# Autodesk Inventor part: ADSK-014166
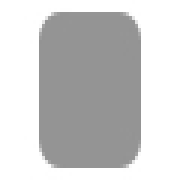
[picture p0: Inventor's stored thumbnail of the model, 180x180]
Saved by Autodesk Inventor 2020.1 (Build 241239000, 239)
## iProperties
Created: 2019-01
Part Number: ADSK-014166
Material: Stahl, weich
Document SubType Name: Modeling
Designer: lutzd
Language: de-DE
Size Designation: 5 x 60 x 40
Categories: <MemberInstance><Categories><Category DisplayName="Sonstige Bauteile" InternalName="5aa15e00-363f-49f2-933f-16f664388e3f" Mnemonic="OTHER"><Category DisplayName
Mass: 93.3577 g
Surface Area: 57.1416 cm^2
Volume: 11.8927 cm^3
Density: 7.85 g/cm^3
Appearance: Halbpoliert
Dimensions: 40x60x5 mm
Mass: 0,093 kg
DocNumber: ADSK-014166
Folder: 01 - Themengebiete\Simplification\01 - Packaging machine\
VDS_Category: 3D Komponenten
VDS_NumSchm: Autodesk
IsCustomPart: 1
Title: end cap
Author: lutzd
Revision Number: -
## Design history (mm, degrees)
sketch "Sketch1"
  geometry: L1 (0, 20.175)-(0, -21.446); L2 (-20.203, 0)-(20.169, 0); L3 (-20, 30)-(20, 30); L4 (20, 30)-(20, -30); L5 (20, -30)-(-20, -30); L6 (-20, -30)-(-20, 30); 1 further point
  constraints: 12 end point, 2 horizontal, 2 parallel, 2 point on line, 1 perpendicular, 1 vertical
  dimensions: "d0" = 60 distance between parallel lines of L5 L3 (= height); "d1" = 30 distance between parallel lines of L2 L3 (= 0.5 x height); "d2" = 40 distance between parallel lines of L6 L4 (= width); "d3" = 20 distance between parallel lines of L6 L1 (= 0.5 x width)
extrude "Extrusion1" new body sketch "Sketch1" distance "d4" = 5 (= thickness); taper "d5" = 0 deg
fillet "Fillet1" dims "d6" = 5 (= fillet), "d7" = 0, "fillet" = 5 [user parameter; used in 1 equation term]
chamfer "Chamfer1" distance "d8" = 0 (computed from chamfer); stored, may be unused: second distance "d9" = 2, angle "d10" = 45 deg; dims "d11" = 0, "chamfer" = 0 [user parameter; used in 1 equation term]
body "Solid1"
other parameters: "thickness" = 5 [user parameter; used in 1 equation term], "width" = 40 [user parameter; used in 2 equation terms], "height" = 60 [user parameter; used in 2 equation terms]
